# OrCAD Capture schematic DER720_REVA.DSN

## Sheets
1 PAGE1: size C; title: DER720; rev: A
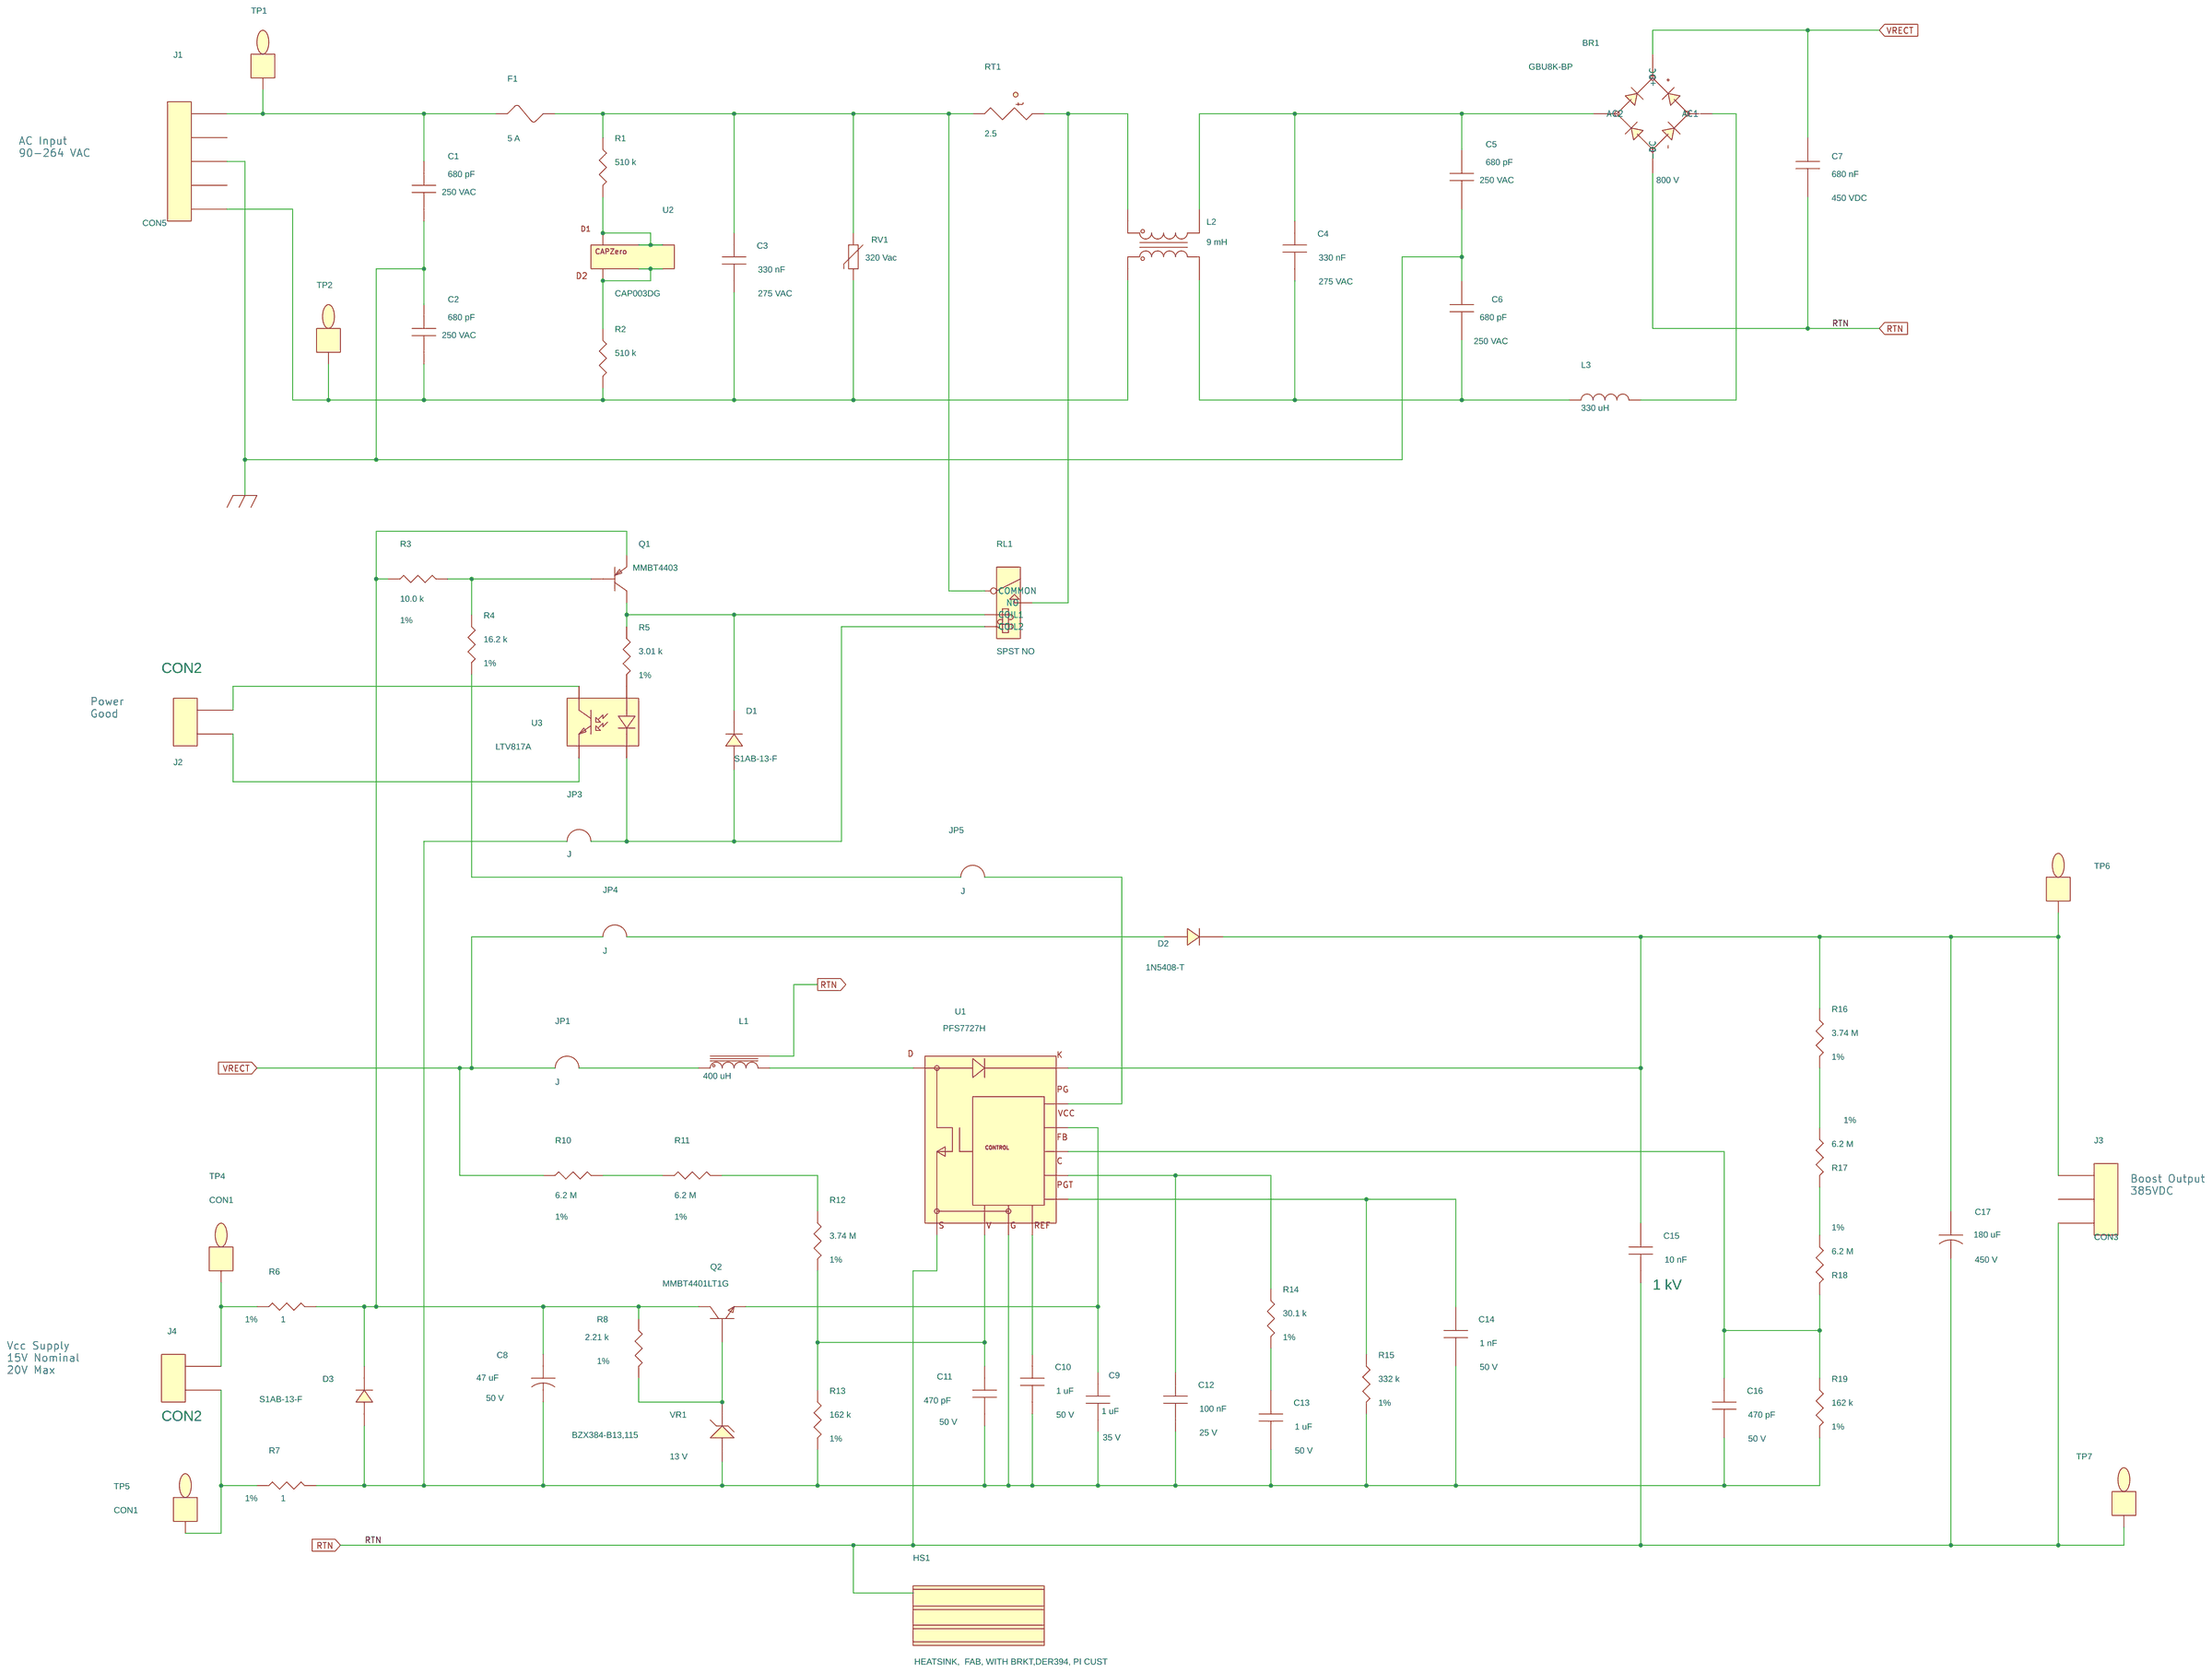
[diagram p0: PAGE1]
2 PAGE2: size C
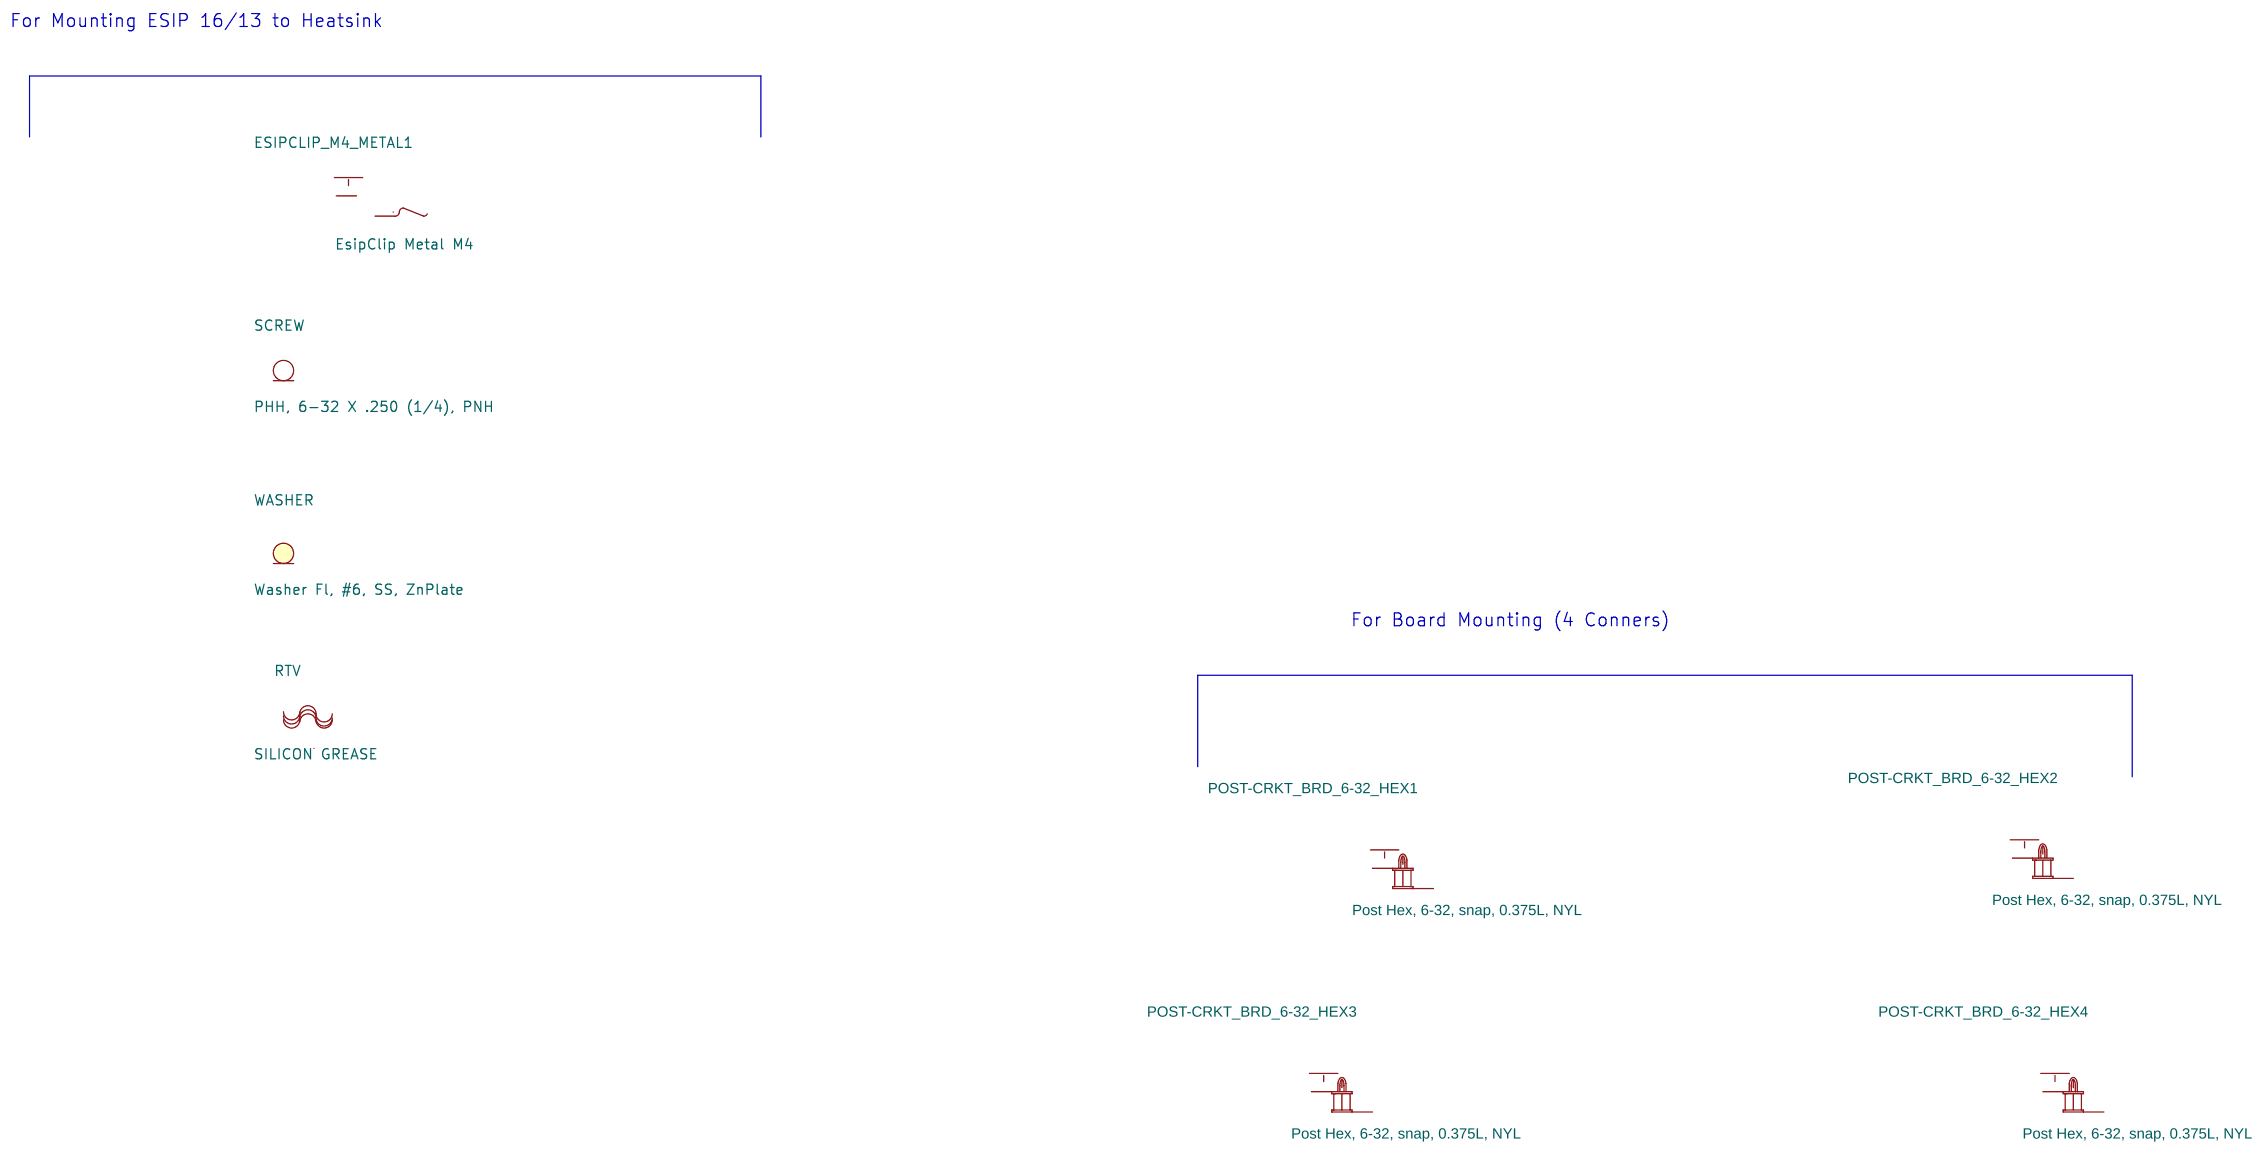
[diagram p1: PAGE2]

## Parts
sheet PAGE1
BR1  GBU8K-BP  [pidaxbridgegbu8]
C1  680 pF  [pinpycaprad470x210ls380040]
C2  680 pF  [pinpycaprad470x210ls380040]
C3  330 nF  [pinpcaprad760x380590050]
C4  330 nF  [pinpcaprad760x380590050]
C5  680 pF  [pinpycaprad470x210ls380040]
C6  680 pF  [pinpycaprad470x210ls380040]
C7  680 nF  [pi_np_cap_rad717x272ls590d050]
C8  47 uF  [pipolcapcyld250ls100030]
C9  1 uF  [pismc0603]
C10  1 uF  [pismc0805]
C11  470 pF  [pismc0805]
C12  100 nF  [pismc0805]
C13  1 uF  [pismc0805]
C14  1 nF  [pismc0805]
C15  10 nF  [pi_np_cap250x200ls170d030]
C16  470 pF  [pismc0805]
C17  180 uF  [pipolcapclyd985ls394086]
D1  S1AB-13-F  [pismsmb]
D2  1N5408-T  [pidax800x225060do15do201ad]
D3  S1AB-13-F  [pismsmb]
F1  5 A  [pi_tr5_submin_fuse]
HS1  HEATSINK,  FAB, WITH BRKT,DER394, PI CUST  [pi_hs_der394_eesip]
J1  CON5  [pi_hdr_5pin]
J2  CON2  [pi_molex_2pol]
J3  CON3  [pi_hdr_3pin_lock]
J4  CON2  [pi_molex_2pol]
JP1  J  [pi_jumper200]
JP3  J  [pi_jumper200]
JP4  J  [pi_jumper800]
JP5  J  [pi_jumper900]
L1  400 uH  [pi_bobbin_bpq32_20_32-00298-00]
L2  9 mH  [pi_ind_4p_500x1050ls450d46_r1]
L3  330 uH  [pi_toroid_2p_550x950_ls480_d050]
Q1  MMBT4403  [pismsot23132]
Q2  MMBT4401LT1G  [pismsot23132]
R1  510 k  [pismr1206]
R2  510 k  [pismr1206]
R3  10.0 k  [pismr1206]
R4  16.2 k  [pismr1206]
R5  3.01 k  [pismr1206]
R6  1  [pismr1206]
R7  1  [pismr1206]
R8  2.21 k  [pismr0805]
R10  6.2 M  [pismr1206]
R11  6.2 M  [pismr1206]
R12  3.74 M  [pi14wvresd100ls100d030]
R13  162 k  [pismr0805]
R14  30.1 k  [pismr0805]
R15  332 k  [pismr0805]
R16  3.74 M  [pi14wvresd100ls100d030]
R17  6.2 M  [pismr1206]
R18  6.2 M  [pismr1206]
R19  162 k  [pismr0805]
RL1  SPST NO  [pi_rly-omron-g6rl-1a]
RT1  2.5  [pi_rad180x395ls235d031]
RV1  320 Vac  [pidisc500x225ls335x140040]
TP1  CON1  [pitpkeystone125x125]
TP2  CON1  [pitpkeystone125x125]
TP4  CON1  [pitpkeystone125x125]
TP5  CON1  [pitpkeystone125x125]
TP6  CON1  [pitpkeystone125x125]
TP7  CON1  [pitpkeystone125x125]
U1  PFS7727H  [pi_ic_esip-16D]
U2  CAP003DG  [pi_ic_smd_so8_capzero]
U3  LTV817A  [pi_dip4]
VR1  BZX384-B13,115  [pismsod323]
sheet PAGE2
ESIPCLIP_M4_METAL1  EsipClip Metal M4
POST-CRKT_BRD_6-32_HEX1  Post Hex, 6-32, snap, 0.375L, NYL  [pimtgholed156]
POST-CRKT_BRD_6-32_HEX2  Post Hex, 6-32, snap, 0.375L, NYL  [pimtgholed156]
POST-CRKT_BRD_6-32_HEX3  Post Hex, 6-32, snap, 0.375L, NYL  [pimtgholed156]
POST-CRKT_BRD_6-32_HEX4  Post Hex, 6-32, snap, 0.375L, NYL  [pimtgholed156]
RTV  SILICON GREASE
SCREW  PHH, 6-32 X .250 (1/4), PNH
WASHER  Washer Fl, #6, SS, ZnPlate

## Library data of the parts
BR1 = DISCRETE_BRIDGE_+~~-: Disp_Voltage: 800 V; Part Number: 15-00347-00
C1 C2 C5 C6 = CAP_NP: Disp_Voltage: 250 VAC; Part Number: 20-00374-00; Tol: 20; Voltage: 250 VAC
C3 C4 = CAP_NP: Disp_Voltage: 275 VAC; Part Number: 20-00542-00; Voltage: 275 VAC
C7 = CAP_NP: ALT_SYMBOLS: pi_np_cap_rad717x272ls590d050_h; Disp_Voltage: 450 VDC; FPLIST: pi_np_cap_rad717x272ls590d050,pi_np_cap_rad717x272ls590d050_h; Part Number: 20-08705-00; Voltage: 450 VDC
C8 = CAP_POL: ALT_SYMBOLS: pipolcapcyld250ls100030h; Disp_Voltage: 50 V; Part Number: 20-00444-00; Tol: 20; Voltage: 50 V
C9 = CAP_NP: Disp_Voltage: 35 V; Part Number: 20-01134-00; Voltage: 35 V
C10 C13 = CAP_NP: Disp_Voltage: 50 V; Part Number: 20-01022-00; Voltage: 50 V
C11 C16 = CAP_NP: Disp_Voltage: 50 V; Part Number: 20-00205-00; Voltage: 50 V
C12 = CAP_NP: Disp_Voltage: 25 V; Part Number: 20-08599-00; Voltage: 25 V
C14 = CAP_NP: Disp_Voltage: 50 V; Part Number: 20-08750-00; Voltage: 50 V
C15 = CAP_NP: Disp_Voltage: 1 kV; Part Number: 20-00894-00; Voltage: 1 kV
C17 = CAP_POL: Disp_Voltage: 450 V; Part Number: 20-01129-00; Voltage: 450 V
D1 D3 = DIODE: Part Number: 15-00994-00
D2 = DIODE: ALT_SYMBOLS: pidax800x225060do15do201ad,pidv300x200x060do14wbead; FPLIST: pidv300x200x060do15d0201ad,pidax800x225060do15do201ad,pidv300x200x060do14wbead; Part Number: 15-00719-00
F1 = FUSE: Part Number: 40-00005-00
HS1 = HS-PI_CUSTOM2: Part Number: 61-00145-01
J1 = CON5: Part Number: 35-00242-00
J2 J4 = CON2: Part Number: 35-00137-00
J3 = CON3: Part Number: 35-00243-00
JP1 = JUMPER_1: Part Number: 65-00001-00
JP3 = JUMPER_1: Part Number: 65-00119-00
JP4 = JUMPER_1: Part Number: 65-00125-00
JP5 = JUMPER_1: Part Number: 65-00126-00
L1 = INDUCTOR_DER394_32-00298-00: Part Number: 32-00298-00
L2 = INDUCTOR_4P_revB: FPLIST: pi_ind_4p_500x1050ls450d46,pi_ind_4p_500x1050ls450d46_r1; Part Number: 30-00235-00
L3 = INDUCTOR: Part Number: 32-00295-00
Q1 = PNP_BEC: Part Number: 55-00060-00
Q2 = NPN_BEC: Part Number: 55-00059-00
R1 R2 = R: Part Number: 05-01417-00
R3 = R: Disp_Tol: 1%; Part Number: 05-00289-00
R4 = R: Disp_Tol: 1%; Part Number: 05-00309-00
R5 = R: Disp_Tol: 1%; Part Number: 05-00239-00
R6 R7 = R: Disp_Tol: 1%; Part Number: 05-00481-00
R8 = R: Disp_Tol: 1%; Part Number: 05-03341-00
R10 R11 R17 R18 = R: Disp_Tol: 1%; Part Number: 05-05567-00
R12 R16 = R: ALT_SYMBOLS: pi14wvresd100ls200d030,pi14wresd100ls400d030,pi14wresd100ls500d030; Disp_Tol: 1%; FPLIST: pi14wvresd100ls100d030,pi14wvresd100ls200d030,pi14wresd100ls400d030,pi14wresd100ls500d030; Part Number: 05-05566-00
R13 R19 = R: Disp_Tol: 1%; Part Number: 05-00800-00
R14 = R: Disp_Tol: 1%; Part Number: 05-00730-00
R15 = R: Disp_Tol: 1%; Part Number: 05-00830-00
RL1 = RELAY_SPST_NO_OMRON-G6RL: Part Number: 66-00123-00
RT1 = THERMISTOR: FPLIST: pi_rad180x395ls235d031,pirad550x410ls300040_h; Part Number: 90-00038-00
RV1 = VARISTOR: Part Number: 85-00018-00
TP1 TP5 TP7 = TESTPOINT: Part Number: 35-00042-00
TP2 = TESTPOINT: Part Number: 35-00044-00
TP4 TP6 = TESTPOINT: Part Number: 35-00043-00
U1 = HIPERPFS-4-eSIP-16D_16K: ALT_SYMBOLS: piiclbendesiplg_socket; Part Number: 10-01283-00
U2 = CAPZero: Part Number: 10-00391-00
U3 = OPTO_DIP: Part Number: 53-00008-00
VR1 = DIODE_ZENER: Disp_Voltage: 13 V; Part Number: 15-00819-00
ESIPCLIP_M4_METAL1 = EsipClip_Metal_M4: Part Number: 60-00042-00
POST-CRKT_BRD_6-32_HEX1-POST-CRKT_BRD_6-32_HEX4 = POST_CRKT_BRD_6-32_HEX: Part Number: 76-00003-00
RTV = RTV: Part Number: 66-00084-00
SCREW = SCR_6-32: Part Number: 75-00007-00
WASHER = WASH_FLAT_6: Part Number: 75-00167-00

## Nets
GND_EARTH: C1.2 C2.1 C5.2 C6.1 J1.3
RTN: BR1.4(-DC) C7.2 C15.2 C17.2 HS1.2 J3.3 L1.8 TP7.1 U1.10
VRECT: BR1.1(+DC) C7.1 JP1.1 JP4.1 R10.1
N07467: C15.1 C17.1 D2.1 J3.1 R16.1 TP6.1 U1.16
N25080: C8.1 D3.1 Q1.2(EMITTER) Q2.3(COLLECTOR) R3.1 R6.2 R8.1
N182027: C8.2 C9.2 C10.2 C11.2 C12.2 C13.2 C14.2 C16.2 D3.2 JP3.1 R7.2 R13.2 R15.2 R19.2 U1.4 VR1.2
N186578: J4.1 R6.1 TP4.1
N737447: J4.2 R7.1 TP5.1
N1270725: C2.2 C3.2 J1.5 L2.1 R2.2 RV1.2 TP2.1
N1270759: BR1.3(AC2) C4.1 C5.1 L2.4
N1270767: C4.2 C6.2 L2.2 L3.1
N1270943: BR1.2(AC1) L3.2
N1271019: R1.2 U2.1(NC1) U2.2(D1) U2.3(NC2) U2.4(NC3)
N1271113: C3.1 F1.2 R1.1 RL1.3(COMMON) RT1.1 RV1.1
N1271129: C1.1 F1.1 J1.1 TP1.1
N1844572: D1.2 JP3.2 RL1.2(COIL2) U3.2(C)
N1847765: Q1.1(BASE) R3.2 R4.1
N1847834: JP5.1 R4.2
N1847930: D1.1 Q1.3(COLLECTOR) R5.1 RL1.1(COIL1)
N1948021: J2.1 U3.3(E)
N1951038: J2.2 U3.4(Collector)
N2021552: R2.1 U2.5(NC4) U2.6(NC5) U2.7(D2) U2.8(NC8)
N2052551: L2.3 RL1.4(NO) RT1.2
N2109009: R16.2 R17.2
N2109013: R17.1 R18.2
N2109017: C16.1 R18.1 R19.1 U1.7
N2109281: JP5.2 U1.8
N2110258: C9.1 Q2.2(EMITTER) U1.1
N2110453: C13.1 R14.2
N2110457: C12.1 R14.1 U1.6
N2110757: C10.1 U1.3
N2114150: R10.2 R11.1
N2114158: R11.2 R12.1
N2114457: C11.1 R12.2 R13.1 U1.5
N2158177: C14.1 R15.1 U1.9
N2163226: JP1.2 L1.1
N2199044: Q2.1(BASE) R8.2 VR1.1
N2237206: L1.6 U1.13
N2267541: D2.2 JP4.2
N2274417: R5.2 U3.1(A)

Not connected (* = marked no-connect by the designer): HS1 1; J1 2 4; J3 2; POST-CRKT_BRD_6-32_HEX1 1; POST-CRKT_BRD_6-32_HEX2 1; POST-CRKT_BRD_6-32_HEX3 1; POST-CRKT_BRD_6-32_HEX4 1; U1 11

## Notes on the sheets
sheet 1
- AC Input
  90-264 VAC
- Power
  Good
- Boost Output
  385VDC
- Vcc Supply
  15V Nominal
  20V Max
sheet 2
- For Mounting ESIP 16/13 to Heatsink
- For Board Mounting (4 Conners)
